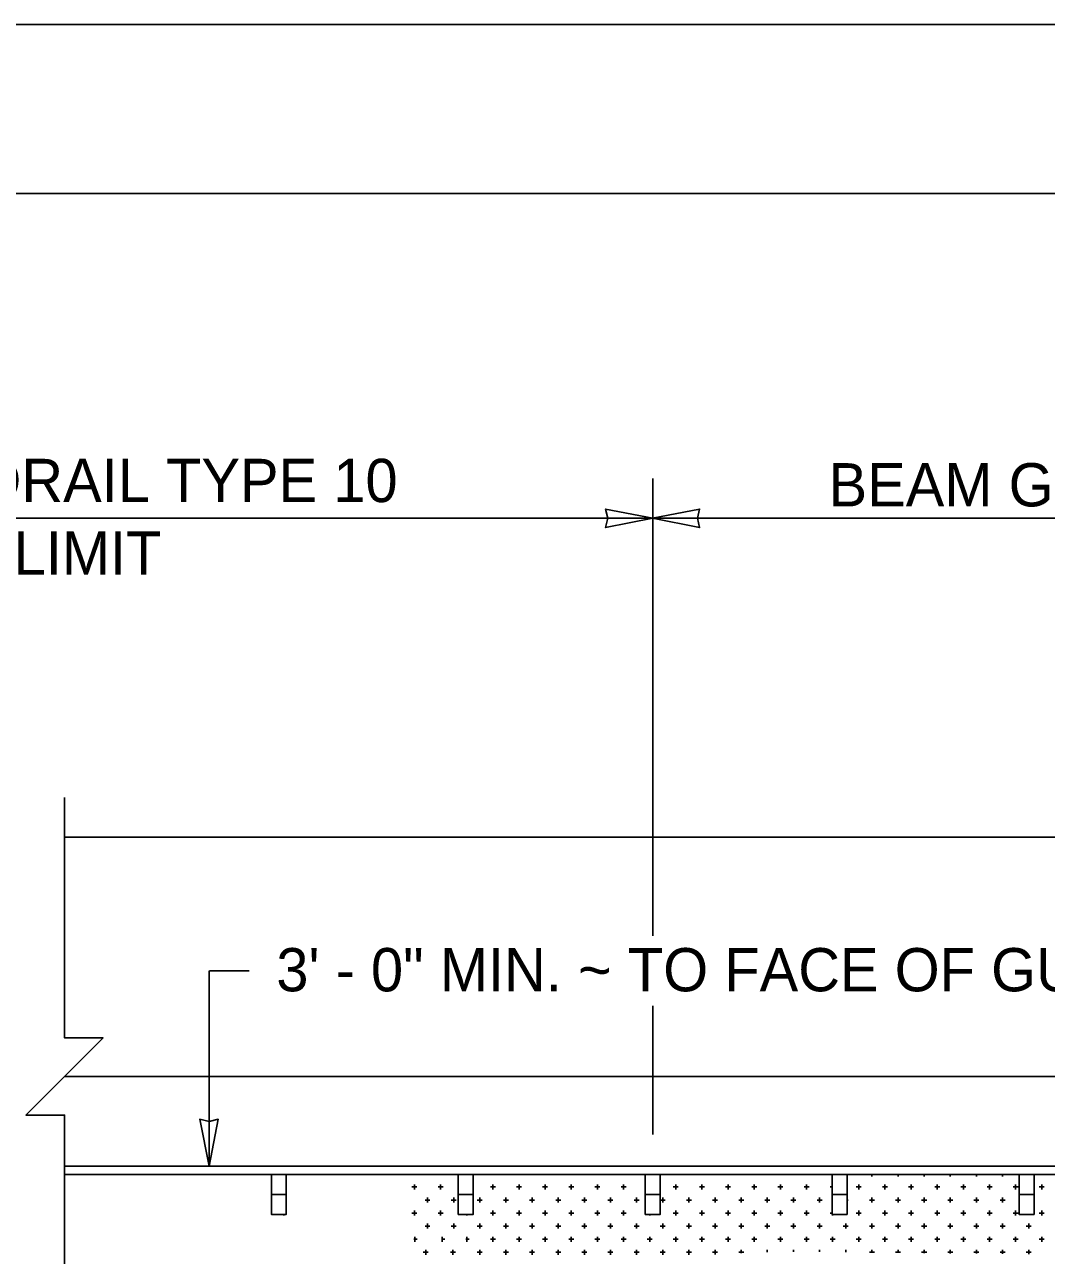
# Model space of a CAD drawing. Extents: x 1312564.5 to 1312581.5, y 1207298.4 to 1207309.4.
# Drawn here: x 1312570.114 to 1312572.003, y 1207307.145 to 1207309.421 of the extents above; entities that cross this region are included whole.
import ezdxf

# ---------------------------------------------------------------- set-up
doc = ezdxf.new("R2010")
doc.units = 0
for name, color, linetype in [('Level 15', 7, 'Continuous'), ('Level 2', 7, 'Continuous'), ('Level 20', 7, 'Continuous'), ('Level 3', 7, 'Continuous'), ('Level 4', 7, 'Continuous'), ('Level 44', 7, 'Continuous'), ('SH_GI_PlotLimits', 7, 'Continuous'), ('SH_GI_SheetBorder', 7, 'Continuous')]:
    doc.layers.add(name, color=color, linetype=linetype)

msp = doc.modelspace()

# ---------------------------------------------------------------- linework, layer by layer
at = {"layer": 'Level 15'}
for p, q in [((1312570.4545, 1207307.31), (1312570.4545, 1207307.6713)), ((1312570.4552, 1207307.6713), (1312570.5289, 1207307.6713))]:
    msp.add_line(p, q, dxfattribs=at)
for points in [[(1312571.2748, 1207308.5818), (1312571.2748, 1207307.7359)], [(1312568.9523, 1207308.5081), (1312571.2748, 1207308.5081)], [(1312574.1624, 1207308.5081), (1312571.2748, 1207308.5081)], [(1312570.1873, 1207307.992), (1312570.1873, 1207307.5473), (1312570.2586, 1207307.5473), (1312570.1159, 1207307.4046), (1312570.1873, 1207307.4046), (1312570.1873, 1207306.8953)], [(1312571.2748, 1207307.6068), (1312571.2748, 1207307.3685)]]:
    msp.add_lwpolyline(points, dxfattribs=at)
for points in [[(1312571.2748, 1207308.5081), (1312571.1878, 1207308.4911), (1312571.1918, 1207308.5081), (1312571.1878, 1207308.5252)], [(1312571.2744, 1207308.5081), (1312571.3614, 1207308.491), (1312571.3574, 1207308.5081), (1312571.3614, 1207308.5251)], [(1312570.4545, 1207307.31), (1312570.4374, 1207307.397), (1312570.4545, 1207307.393), (1312570.4715, 1207307.397)]]:
    msp.add_lwpolyline(points, close=True, dxfattribs=at)
at = {"layer": 'Level 2'}
for p, q in [((1312570.1873, 1207307.31), (1312573.3484, 1207307.31)), ((1312570.1873, 1207307.2948), (1312573.3484, 1207307.2948)), ((1312571.68, 1207307.2914), (1312571.68, 1207307.2948)), ((1312571.7283, 1207307.2914), (1312571.7283, 1207307.2948)), ((1312571.7766, 1207307.2914), (1312571.7766, 1207307.2948)), ((1312571.825, 1207307.2914), (1312571.825, 1207307.2948)), ((1312571.8733, 1207307.2914), (1312571.8733, 1207307.2948)), ((1312571.9216, 1207307.2914), (1312571.9216, 1207307.2948)), ((1312571.6029, 1207307.2719), (1312571.6065, 1207307.2719)), ((1312571.5787, 1207307.2477), (1312571.588, 1207307.2477)), ((1312571.5833, 1207307.2431), (1312571.5833, 1207307.2523)), ((1312571.6342, 1207307.2477), (1312571.6363, 1207307.2477)), ((1312570.5926, 1207307.2189), (1312570.5926, 1207307.221)), ((1312570.9309, 1207307.2189), (1312570.9309, 1207307.221)), ((1312571.2692, 1207307.2189), (1312571.2692, 1207307.221)), ((1312571.6029, 1207307.2235), (1312571.6065, 1207307.2235)), ((1312571.6075, 1207307.2189), (1312571.6075, 1207307.221))]:
    msp.add_line(p, q, dxfattribs=at)
for points in [[(1312570.5974, 1207307.2948), (1312570.5697, 1207307.2948), (1312570.5697, 1207307.2579), (1312570.5974, 1207307.2579)], [(1312570.943, 1207307.2948), (1312570.9153, 1207307.2948), (1312570.9153, 1207307.2579), (1312570.943, 1207307.2579)], [(1312571.2886, 1207307.2948), (1312571.2609, 1207307.2948), (1312571.2609, 1207307.2579), (1312571.2886, 1207307.2579)], [(1312571.6342, 1207307.2948), (1312571.6065, 1207307.2948), (1312571.6065, 1207307.2579), (1312571.6342, 1207307.2579)], [(1312571.9798, 1207307.2948), (1312571.9521, 1207307.2948), (1312571.9521, 1207307.2579), (1312571.9798, 1207307.2579)], [(1312570.5974, 1207307.2579), (1312570.5697, 1207307.2579), (1312570.5697, 1207307.221), (1312570.5974, 1207307.221)], [(1312570.943, 1207307.2579), (1312570.9153, 1207307.2579), (1312570.9153, 1207307.221), (1312570.943, 1207307.221)], [(1312571.2886, 1207307.2579), (1312571.2609, 1207307.2579), (1312571.2609, 1207307.221), (1312571.2886, 1207307.221)], [(1312571.6342, 1207307.2579), (1312571.6065, 1207307.2579), (1312571.6065, 1207307.221), (1312571.6342, 1207307.221)], [(1312571.9798, 1207307.2579), (1312571.9521, 1207307.2579), (1312571.9521, 1207307.221), (1312571.9798, 1207307.221)]]:
    msp.add_lwpolyline(points, close=True, dxfattribs=at)
at = {"layer": 'Level 3'}
msp.add_line((1312570.1873, 1207307.4759), (1312574.4389, 1207307.4759), dxfattribs=at)
at = {"layer": 'Level 4'}
for p, q in [((1312570.8297, 1207307.2719), (1312570.8389, 1207307.2719)), ((1312570.8343, 1207307.2673), (1312570.8343, 1207307.2765)), ((1312570.878, 1207307.2719), (1312570.8872, 1207307.2719)), ((1312570.8826, 1207307.2673), (1312570.8826, 1207307.2765)), ((1312570.9746, 1207307.2719), (1312570.9839, 1207307.2719)), ((1312570.9793, 1207307.2673), (1312570.9793, 1207307.2765)), ((1312571.023, 1207307.2719), (1312571.0276, 1207307.2719)), ((1312571.0276, 1207307.2673), (1312571.0276, 1207307.2765)), ((1312571.0276, 1207307.2719), (1312571.0322, 1207307.2719)), ((1312571.0713, 1207307.2719), (1312571.0805, 1207307.2719)), ((1312571.0759, 1207307.2673), (1312571.0759, 1207307.2765)), ((1312571.1196, 1207307.2719), (1312571.1288, 1207307.2719)), ((1312571.1242, 1207307.2673), (1312571.1242, 1207307.2765)), ((1312571.168, 1207307.2719), (1312571.1772, 1207307.2719)), ((1312571.1726, 1207307.2673), (1312571.1726, 1207307.2765)), ((1312571.2163, 1207307.2719), (1312571.2255, 1207307.2719)), ((1312571.2209, 1207307.2673), (1312571.2209, 1207307.2765)), ((1312571.3129, 1207307.2719), (1312571.3175, 1207307.2719)), ((1312571.3175, 1207307.2673), (1312571.3175, 1207307.2765)), ((1312571.3175, 1207307.2719), (1312571.3221, 1207307.2719)), ((1312571.3613, 1207307.2719), (1312571.3705, 1207307.2719)), ((1312571.3659, 1207307.2673), (1312571.3659, 1207307.2765)), ((1312571.4096, 1207307.2719), (1312571.4188, 1207307.2719)), ((1312571.4142, 1207307.2673), (1312571.4142, 1207307.2765)), ((1312571.4579, 1207307.2719), (1312571.4671, 1207307.2719)), ((1312571.4625, 1207307.2673), (1312571.4625, 1207307.2765)), ((1312571.5062, 1207307.2719), (1312571.5155, 1207307.2719)), ((1312571.5109, 1207307.2673), (1312571.5109, 1207307.2765)), ((1312571.5546, 1207307.2719), (1312571.5638, 1207307.2719)), ((1312571.5592, 1207307.2673), (1312571.5592, 1207307.2765)), ((1312571.6512, 1207307.2719), (1312571.6604, 1207307.2719)), ((1312571.6558, 1207307.2673), (1312571.6558, 1207307.2765)), ((1312571.6995, 1207307.2719), (1312571.7088, 1207307.2719)), ((1312571.7042, 1207307.2673), (1312571.7042, 1207307.2765)), ((1312571.7479, 1207307.2719), (1312571.7571, 1207307.2719)), ((1312571.7525, 1207307.2673), (1312571.7525, 1207307.2765)), ((1312571.7962, 1207307.2719), (1312571.8054, 1207307.2719)), ((1312571.8008, 1207307.2673), (1312571.8008, 1207307.2765)), ((1312571.8445, 1207307.2719), (1312571.8537, 1207307.2719)), ((1312571.8491, 1207307.2673), (1312571.8491, 1207307.2765)), ((1312571.8929, 1207307.2719), (1312571.8975, 1207307.2719)), ((1312571.8975, 1207307.2673), (1312571.8975, 1207307.2765)), ((1312571.8975, 1207307.2719), (1312571.9021, 1207307.2719)), ((1312571.9412, 1207307.2719), (1312571.9504, 1207307.2719)), ((1312571.9458, 1207307.2673), (1312571.9458, 1207307.2765)), ((1312571.9895, 1207307.2719), (1312571.9987, 1207307.2719)), ((1312571.9941, 1207307.2673), (1312571.9941, 1207307.2765)), ((1312570.8538, 1207307.2477), (1312570.863, 1207307.2477)), ((1312570.8584, 1207307.2431), (1312570.8584, 1207307.2523)), ((1312570.9022, 1207307.2477), (1312570.9114, 1207307.2477)), ((1312570.9068, 1207307.2431), (1312570.9068, 1207307.2523)), ((1312570.9505, 1207307.2477), (1312570.9597, 1207307.2477)), ((1312570.9551, 1207307.2431), (1312570.9551, 1207307.2523)), ((1312570.9988, 1207307.2477), (1312571.008, 1207307.2477)), ((1312571.0034, 1207307.2431), (1312571.0034, 1207307.2523)), ((1312571.0471, 1207307.2477), (1312571.0563, 1207307.2477)), ((1312571.0517, 1207307.2431), (1312571.0517, 1207307.2523)), ((1312571.0955, 1207307.2477), (1312571.1047, 1207307.2477)), ((1312571.1001, 1207307.2431), (1312571.1001, 1207307.2523)), ((1312571.1438, 1207307.2477), (1312571.153, 1207307.2477)), ((1312571.1484, 1207307.2431), (1312571.1484, 1207307.2523)), ((1312571.1921, 1207307.2477), (1312571.2013, 1207307.2477)), ((1312571.1967, 1207307.2431), (1312571.1967, 1207307.2523)), ((1312571.2404, 1207307.2477), (1312571.2497, 1207307.2477)), ((1312571.2451, 1207307.2431), (1312571.2451, 1207307.2523)), ((1312571.2888, 1207307.2477), (1312571.298, 1207307.2477)), ((1312571.2934, 1207307.2431), (1312571.2934, 1207307.2523)), ((1312571.3371, 1207307.2477), (1312571.3463, 1207307.2477)), ((1312571.3417, 1207307.2431), (1312571.3417, 1207307.2523)), ((1312571.3854, 1207307.2477), (1312571.3946, 1207307.2477)), ((1312571.39, 1207307.2431), (1312571.39, 1207307.2523)), ((1312571.4338, 1207307.2477), (1312571.443, 1207307.2477)), ((1312571.4384, 1207307.2431), (1312571.4384, 1207307.2523)), ((1312571.4821, 1207307.2477), (1312571.4913, 1207307.2477)), ((1312571.4867, 1207307.2431), (1312571.4867, 1207307.2523)), ((1312571.5304, 1207307.2477), (1312571.5396, 1207307.2477)), ((1312571.535, 1207307.2431), (1312571.535, 1207307.2523)), ((1312571.6754, 1207307.2477), (1312571.6846, 1207307.2477)), ((1312571.68, 1207307.2431), (1312571.68, 1207307.2523)), ((1312571.7237, 1207307.2477), (1312571.7329, 1207307.2477)), ((1312571.7283, 1207307.2431), (1312571.7283, 1207307.2523)), ((1312571.772, 1207307.2477), (1312571.7813, 1207307.2477)), ((1312571.7766, 1207307.2431), (1312571.7766, 1207307.2523)), ((1312571.8204, 1207307.2477), (1312571.8296, 1207307.2477)), ((1312571.825, 1207307.2431), (1312571.825, 1207307.2523)), ((1312571.8687, 1207307.2477), (1312571.8779, 1207307.2477)), ((1312571.8733, 1207307.2431), (1312571.8733, 1207307.2523)), ((1312571.917, 1207307.2477), (1312571.9262, 1207307.2477)), ((1312571.9216, 1207307.2431), (1312571.9216, 1207307.2523)), ((1312570.8297, 1207307.2235), (1312570.8389, 1207307.2235)), ((1312570.8343, 1207307.2189), (1312570.8343, 1207307.2282)), ((1312570.878, 1207307.2235), (1312570.8872, 1207307.2235)), ((1312570.8826, 1207307.2189), (1312570.8826, 1207307.2282)), ((1312570.9746, 1207307.2235), (1312570.9839, 1207307.2235)), ((1312570.9793, 1207307.2189), (1312570.9793, 1207307.2282)), ((1312571.023, 1207307.2235), (1312571.0276, 1207307.2235)), ((1312571.0276, 1207307.2189), (1312571.0276, 1207307.2282)), ((1312571.0276, 1207307.2235), (1312571.0322, 1207307.2235)), ((1312571.0713, 1207307.2235), (1312571.0805, 1207307.2235)), ((1312571.0759, 1207307.2189), (1312571.0759, 1207307.2282)), ((1312571.1196, 1207307.2235), (1312571.1288, 1207307.2235)), ((1312571.1242, 1207307.2189), (1312571.1242, 1207307.2282)), ((1312571.168, 1207307.2235), (1312571.1772, 1207307.2235)), ((1312571.1726, 1207307.2189), (1312571.1726, 1207307.2282)), ((1312571.2163, 1207307.2235), (1312571.2255, 1207307.2235)), ((1312571.2209, 1207307.2189), (1312571.2209, 1207307.2282)), ((1312571.3129, 1207307.2235), (1312571.3175, 1207307.2235)), ((1312571.3175, 1207307.2189), (1312571.3175, 1207307.2282)), ((1312571.3175, 1207307.2235), (1312571.3221, 1207307.2235)), ((1312571.3613, 1207307.2235), (1312571.3705, 1207307.2235)), ((1312571.3659, 1207307.2189), (1312571.3659, 1207307.2282)), ((1312571.4096, 1207307.2235), (1312571.4188, 1207307.2235)), ((1312571.4142, 1207307.2189), (1312571.4142, 1207307.2282)), ((1312571.4579, 1207307.2235), (1312571.4671, 1207307.2235)), ((1312571.4625, 1207307.2189), (1312571.4625, 1207307.2282)), ((1312571.5062, 1207307.2235), (1312571.5155, 1207307.2235)), ((1312571.5109, 1207307.2189), (1312571.5109, 1207307.2282)), ((1312571.5546, 1207307.2235), (1312571.5638, 1207307.2235)), ((1312571.5592, 1207307.2189), (1312571.5592, 1207307.2282)), ((1312571.6512, 1207307.2235), (1312571.6604, 1207307.2235)), ((1312571.6558, 1207307.2189), (1312571.6558, 1207307.2282)), ((1312571.6995, 1207307.2235), (1312571.7088, 1207307.2235)), ((1312571.7042, 1207307.2189), (1312571.7042, 1207307.2282)), ((1312571.7479, 1207307.2235), (1312571.7571, 1207307.2235)), ((1312571.7525, 1207307.2189), (1312571.7525, 1207307.2282)), ((1312571.7962, 1207307.2235), (1312571.8054, 1207307.2235)), ((1312571.8008, 1207307.2189), (1312571.8008, 1207307.2282)), ((1312571.8445, 1207307.2235), (1312571.8537, 1207307.2235)), ((1312571.8491, 1207307.2189), (1312571.8491, 1207307.2282)), ((1312571.8929, 1207307.2235), (1312571.8975, 1207307.2235)), ((1312571.8975, 1207307.2189), (1312571.8975, 1207307.2282)), ((1312571.8975, 1207307.2235), (1312571.9021, 1207307.2235)), ((1312571.9412, 1207307.2235), (1312571.9504, 1207307.2235)), ((1312571.9458, 1207307.2189), (1312571.9458, 1207307.2282)), ((1312571.9895, 1207307.2235), (1312571.9987, 1207307.2235)), ((1312571.9941, 1207307.2189), (1312571.9941, 1207307.2282)), ((1312570.8538, 1207307.1994), (1312570.863, 1207307.1994)), ((1312570.8584, 1207307.1948), (1312570.8584, 1207307.204)), ((1312570.9022, 1207307.1994), (1312570.9114, 1207307.1994)), ((1312570.9068, 1207307.1948), (1312570.9068, 1207307.204)), ((1312570.9505, 1207307.1994), (1312570.9597, 1207307.1994)), ((1312570.9551, 1207307.1948), (1312570.9551, 1207307.204)), ((1312570.9988, 1207307.1994), (1312571.008, 1207307.1994)), ((1312571.0034, 1207307.1948), (1312571.0034, 1207307.204)), ((1312571.0471, 1207307.1994), (1312571.0563, 1207307.1994)), ((1312571.0517, 1207307.1948), (1312571.0517, 1207307.204)), ((1312571.0955, 1207307.1994), (1312571.1047, 1207307.1994)), ((1312571.1001, 1207307.1948), (1312571.1001, 1207307.204)), ((1312571.1438, 1207307.1994), (1312571.153, 1207307.1994)), ((1312571.1484, 1207307.1948), (1312571.1484, 1207307.204)), ((1312571.1921, 1207307.1994), (1312571.2013, 1207307.1994)), ((1312571.1967, 1207307.1948), (1312571.1967, 1207307.204)), ((1312571.2404, 1207307.1994), (1312571.2497, 1207307.1994)), ((1312571.2451, 1207307.1948), (1312571.2451, 1207307.204)), ((1312571.2888, 1207307.1994), (1312571.298, 1207307.1994)), ((1312571.2934, 1207307.1948), (1312571.2934, 1207307.204)), ((1312571.3371, 1207307.1994), (1312571.3463, 1207307.1994)), ((1312571.3417, 1207307.1948), (1312571.3417, 1207307.204)), ((1312571.3854, 1207307.1994), (1312571.3946, 1207307.1994)), ((1312571.39, 1207307.1948), (1312571.39, 1207307.204)), ((1312571.4338, 1207307.1994), (1312571.443, 1207307.1994)), ((1312571.4384, 1207307.1948), (1312571.4384, 1207307.204)), ((1312571.4821, 1207307.1994), (1312571.4913, 1207307.1994)), ((1312571.4867, 1207307.1948), (1312571.4867, 1207307.204)), ((1312571.5304, 1207307.1994), (1312571.5396, 1207307.1994)), ((1312571.535, 1207307.1948), (1312571.535, 1207307.204)), ((1312571.5787, 1207307.1994), (1312571.588, 1207307.1994)), ((1312571.5833, 1207307.1948), (1312571.5833, 1207307.204)), ((1312571.6271, 1207307.1994), (1312571.6363, 1207307.1994)), ((1312571.6317, 1207307.1948), (1312571.6317, 1207307.204)), ((1312571.6754, 1207307.1994), (1312571.6846, 1207307.1994)), ((1312571.68, 1207307.1948), (1312571.68, 1207307.204)), ((1312571.7237, 1207307.1994), (1312571.7329, 1207307.1994)), ((1312571.7283, 1207307.1948), (1312571.7283, 1207307.204)), ((1312571.772, 1207307.1994), (1312571.7813, 1207307.1994)), ((1312571.7766, 1207307.1948), (1312571.7766, 1207307.204)), ((1312571.8204, 1207307.1994), (1312571.8296, 1207307.1994)), ((1312571.825, 1207307.1948), (1312571.825, 1207307.204)), ((1312571.8687, 1207307.1994), (1312571.8779, 1207307.1994)), ((1312571.8733, 1207307.1948), (1312571.8733, 1207307.204)), ((1312571.917, 1207307.1994), (1312571.9262, 1207307.1994)), ((1312571.9216, 1207307.1948), (1312571.9216, 1207307.204)), ((1312571.9653, 1207307.1994), (1312571.9746, 1207307.1994)), ((1312571.97, 1207307.1948), (1312571.97, 1207307.204)), ((1312570.8331, 1207307.1752), (1312570.8395, 1207307.1752)), ((1312570.8349, 1207307.1706), (1312570.8349, 1207307.1798)), ((1312570.8841, 1207307.1752), (1312570.8904, 1207307.1752)), ((1312570.8858, 1207307.1706), (1312570.8858, 1207307.1798)), ((1312570.9292, 1207307.1752), (1312570.9355, 1207307.1752)), ((1312570.9309, 1207307.1706), (1312570.9309, 1207307.1798)), ((1312570.9746, 1207307.1752), (1312570.9839, 1207307.1752)), ((1312570.9793, 1207307.1706), (1312570.9793, 1207307.1798)), ((1312571.023, 1207307.1752), (1312571.0276, 1207307.1752)), ((1312571.0276, 1207307.1706), (1312571.0276, 1207307.1798)), ((1312571.0276, 1207307.1752), (1312571.0322, 1207307.1752)), ((1312571.0713, 1207307.1752), (1312571.0805, 1207307.1752)), ((1312571.0759, 1207307.1706), (1312571.0759, 1207307.1798)), ((1312571.1196, 1207307.1752), (1312571.1288, 1207307.1752)), ((1312571.1242, 1207307.1706), (1312571.1242, 1207307.1798)), ((1312571.168, 1207307.1752), (1312571.1772, 1207307.1752)), ((1312571.1726, 1207307.1706), (1312571.1726, 1207307.1798)), ((1312571.2163, 1207307.1752), (1312571.2255, 1207307.1752)), ((1312571.2209, 1207307.1706), (1312571.2209, 1207307.1798)), ((1312571.2646, 1207307.1752), (1312571.2738, 1207307.1752)), ((1312571.2692, 1207307.1706), (1312571.2692, 1207307.1798)), ((1312571.3129, 1207307.1752), (1312571.3175, 1207307.1752)), ((1312571.3175, 1207307.1706), (1312571.3175, 1207307.1798)), ((1312571.3175, 1207307.1752), (1312571.3221, 1207307.1752)), ((1312571.3613, 1207307.1752), (1312571.3705, 1207307.1752)), ((1312571.3659, 1207307.1706), (1312571.3659, 1207307.1798)), ((1312571.4096, 1207307.1752), (1312571.4188, 1207307.1752)), ((1312571.4142, 1207307.1706), (1312571.4142, 1207307.1798)), ((1312571.4579, 1207307.1752), (1312571.4671, 1207307.1752)), ((1312571.4625, 1207307.1706), (1312571.4625, 1207307.1798)), ((1312571.5062, 1207307.1752), (1312571.5155, 1207307.1752)), ((1312571.5109, 1207307.1706), (1312571.5109, 1207307.1798)), ((1312571.5546, 1207307.1752), (1312571.5638, 1207307.1752)), ((1312571.5592, 1207307.1706), (1312571.5592, 1207307.1798)), ((1312571.6029, 1207307.1752), (1312571.6075, 1207307.1752)), ((1312571.6075, 1207307.1706), (1312571.6075, 1207307.1798)), ((1312571.6075, 1207307.1752), (1312571.6121, 1207307.1752)), ((1312571.6512, 1207307.1752), (1312571.6604, 1207307.1752)), ((1312571.6558, 1207307.1706), (1312571.6558, 1207307.1798)), ((1312571.6995, 1207307.1752), (1312571.7088, 1207307.1752)), ((1312571.7042, 1207307.1706), (1312571.7042, 1207307.1798)), ((1312571.7479, 1207307.1752), (1312571.7571, 1207307.1752)), ((1312571.7525, 1207307.1706), (1312571.7525, 1207307.1798)), ((1312571.7962, 1207307.1752), (1312571.8054, 1207307.1752)), ((1312571.8008, 1207307.1706), (1312571.8008, 1207307.1798)), ((1312571.8445, 1207307.1752), (1312571.8537, 1207307.1752)), ((1312571.8491, 1207307.1706), (1312571.8491, 1207307.1798)), ((1312571.8929, 1207307.1752), (1312571.8975, 1207307.1752)), ((1312571.8975, 1207307.1706), (1312571.8975, 1207307.1798)), ((1312571.8975, 1207307.1752), (1312571.9021, 1207307.1752)), ((1312571.9412, 1207307.1752), (1312571.9504, 1207307.1752)), ((1312571.9458, 1207307.1706), (1312571.9458, 1207307.1798)), ((1312571.9895, 1207307.1752), (1312571.9987, 1207307.1752)), ((1312571.9941, 1207307.1706), (1312571.9941, 1207307.1798)), ((1312570.8506, 1207307.1511), (1312570.8599, 1207307.1511)), ((1312570.8552, 1207307.1464), (1312570.8552, 1207307.1557)), ((1312570.9009, 1207307.1511), (1312570.9101, 1207307.1511)), ((1312570.9055, 1207307.1464), (1312570.9055, 1207307.1557)), ((1312570.9505, 1207307.1511), (1312570.9597, 1207307.1511)), ((1312570.9551, 1207307.1464), (1312570.9551, 1207307.1557)), ((1312570.9988, 1207307.1511), (1312571.008, 1207307.1511)), ((1312571.0034, 1207307.1464), (1312571.0034, 1207307.1557)), ((1312571.0471, 1207307.1511), (1312571.0563, 1207307.1511)), ((1312571.0517, 1207307.1464), (1312571.0517, 1207307.1557)), ((1312571.0955, 1207307.1511), (1312571.1047, 1207307.1511)), ((1312571.1001, 1207307.1464), (1312571.1001, 1207307.1557)), ((1312571.1438, 1207307.1511), (1312571.153, 1207307.1511)), ((1312571.1484, 1207307.1464), (1312571.1484, 1207307.1557)), ((1312571.1921, 1207307.1511), (1312571.2013, 1207307.1511)), ((1312571.1967, 1207307.1464), (1312571.1967, 1207307.1557)), ((1312571.2404, 1207307.1511), (1312571.2497, 1207307.1511)), ((1312571.2451, 1207307.1464), (1312571.2451, 1207307.1557)), ((1312571.2888, 1207307.1511), (1312571.298, 1207307.1511)), ((1312571.2934, 1207307.1464), (1312571.2934, 1207307.1557)), ((1312571.3371, 1207307.1511), (1312571.3463, 1207307.1511)), ((1312571.3417, 1207307.1464), (1312571.3417, 1207307.1557)), ((1312571.3854, 1207307.1511), (1312571.3946, 1207307.1511)), ((1312571.39, 1207307.1469), (1312571.39, 1207307.1557)), ((1312571.4338, 1207307.1511), (1312571.443, 1207307.1511)), ((1312571.4384, 1207307.1497), (1312571.4384, 1207307.1557)), ((1312571.4867, 1207307.1511), (1312571.4867, 1207307.1557)), ((1312571.535, 1207307.1517), (1312571.535, 1207307.1557)), ((1312571.5833, 1207307.1517), (1312571.5833, 1207307.1557)), ((1312571.6317, 1207307.1514), (1312571.6317, 1207307.1557)), ((1312571.6754, 1207307.1511), (1312571.6846, 1207307.1511)), ((1312571.68, 1207307.1509), (1312571.68, 1207307.1557)), ((1312571.7237, 1207307.1511), (1312571.7329, 1207307.1511)), ((1312571.7283, 1207307.1502), (1312571.7283, 1207307.1557)), ((1312571.772, 1207307.1511), (1312571.7813, 1207307.1511)), ((1312571.7766, 1207307.1496), (1312571.7766, 1207307.1557)), ((1312571.8204, 1207307.1511), (1312571.8296, 1207307.1511)), ((1312571.825, 1207307.149), (1312571.825, 1207307.1557)), ((1312571.8687, 1207307.1511), (1312571.8779, 1207307.1511)), ((1312571.8733, 1207307.1485), (1312571.8733, 1207307.1557)), ((1312571.917, 1207307.1511), (1312571.9262, 1207307.1511)), ((1312571.9216, 1207307.148), (1312571.9216, 1207307.1557)), ((1312571.9653, 1207307.1511), (1312571.9746, 1207307.1511)), ((1312571.97, 1207307.1476), (1312571.97, 1207307.1557))]:
    msp.add_line(p, q, dxfattribs=at)
at = {"layer": 'Level 44'}
msp.add_line((1312570.1873, 1207307.9183), (1312574.4389, 1207307.9183), dxfattribs=at)
at = {"layer": 'SH_GI_PlotLimits'}
msp.add_lwpolyline([(1312564.478, 1207298.4209), (1312581.478, 1207298.4209), (1312581.478, 1207309.4209), (1312564.478, 1207309.4209)], close=True, dxfattribs=at)
at = {"layer": 'SH_GI_SheetBorder'}
msp.add_line((1312565.4155, 1207309.1084), (1312581.1655, 1207309.1084), dxfattribs=at)

# ---------------------------------------------------------------- texts
at = {"layer": 'Level 20'}
for s, p in [('BEAM GUARDRAIL TYPE 10', (1312569.3883, 1207308.5381)), ('BEAM GUARDRAIL BULL NOSE TERMINAL', (1312571.5999, 1207308.5301)), ('PAY LIMIT', (1312569.8494, 1207308.4038)), ('3\' - 0" MIN. ~ TO FACE OF GUARDRAIL', (1312570.5789, 1207307.6335))]:
    msp.add_text(s, height=0.08, dxfattribs=at).set_placement(p)

doc.saveas('drawing.dxf')
